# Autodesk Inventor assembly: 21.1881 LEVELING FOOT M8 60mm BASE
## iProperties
Created: 2007-03
Part Number: 21.1881 LEVELING FOOT M8 60mm BASE
Document SubType Name: Assembly
Designer: Andy Moles
Author: Andy Moles
